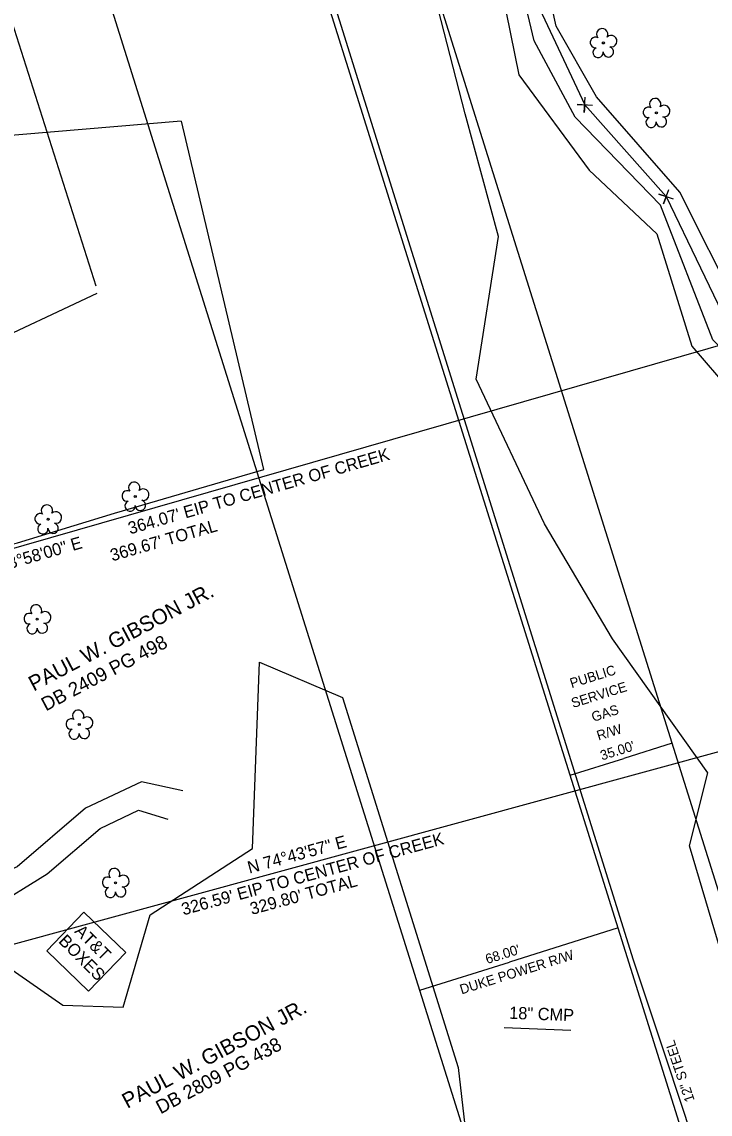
# Model space of a CAD drawing. Extents: x 1380524 to 1382335, y 594765 to 596944.
# Drawn here: x 1381340.7 to 1381565.9, y 595529.8 to 595887.1 of the extents above; entities that cross this region are included whole.
import ezdxf

# ---------------------------------------------------------------- set-up
doc = ezdxf.new("R2010")
doc.units = 0
for name, color, linetype in [('Exist Horizontal Alignment', 7, 'Continuous'), ('Exist Hydro Jurisdictional Stream or Body of Water', 7, 'Continuous'), ('Exist Other Culture Fence Line Text', 7, 'Continuous'), ('Exist Right of Way Line', 7, 'Continuous'), ('Exist Roads EOP', 7, 'Continuous'), ('Exist Structure Major Bridge WW', 7, 'Continuous'), ('Exist Structure Minor Pipes CMP 18 Inch', 7, 'Continuous'), ('Exist Utilities Gas UG Line', 7, 'Continuous'), ('Exist Utilities Gas UG Line SUE', 7, 'Continuous'), ('Exist Utilities Gas UG Line SUE Text', 7, 'Continuous'), ('Exist Utilities Power Tower CELL', 7, 'Continuous'), ('Exist Utilities Power Tower Text', 7, 'Continuous'), ('Prop Approach Slab', 7, 'Continuous'), ('Prop Boundary Easement Permanent Drainage', 7, 'Continuous'), ('Prop Drainage Ditch Base Lines', 7, 'Continuous'), ('Prop Drainage Structure Pipe Elbow CELL', 7, 'Continuous'), ('Prop Drainage Structure Scour Hole CELL', 7, 'Continuous'), ('Prop Earthen Structure Cut Ditch Special Detail Label', 7, 'Continuous'), ('Prop Earthen Structure V Ditch Lateral Detail Label', 7, 'Continuous'), ('Prop Erosion Rip Rap At Embankment Detail CELL', 7, 'Continuous')]:
    doc.layers.add(name, color=color, linetype=linetype)

# ---------------------------------------------------------------- blocks, each defined once
blk = doc.blocks.new('EXIST VEGETATION TREE')
at = {"layer": 'Prop Erosion Rip Rap At Embankment Detail CELL'}
blk.add_line((0, 0), (0, 0), dxfattribs=at)
blk.add_circle((0, 0), 0.00652, dxfattribs=at)
for centre, radius, start, end in [((-0.0077, 0.0575), 0.0371, 330.16508, 219.71335), ((-0.0521, 0.0031), 0.0345, 62.66361, 279.3457), ((0.051, 0.0118), 0.038, 257.1011, 134.19993), ((-0.0341, -0.0624), 0.0338, 111.56708, 6.23104), ((0.0335, -0.058), 0.034, 181.28216, 74.55999)]:
    blk.add_arc(centre, radius, start, end, dxfattribs=at)

msp = doc.modelspace()

# ---------------------------------------------------------------- linework, layer by layer
at = {"layer": 'Exist Horizontal Alignment'}
msp.add_arc((1381427.83, 595653.65), 200, 216.8315, 254.276, dxfattribs=at)
msp.add_arc((1381427.83, 595653.65), 200, 216.8315, 254.276, dxfattribs=at)
msp.add_arc((1381427.83, 595653.65), 200, 216.8315, 254.276, dxfattribs=at)
at = {"layer": 'Exist Hydro Jurisdictional Stream or Body of Water'}
for points in [[(1381577.96, 595605.83), (1381583.71, 595643.65), (1381597.79, 595698.93), (1381598.19, 595737), (1381590.93, 595758.1), (1381566.71, 595783.08), (1381549.63, 595827.2), (1381521.68, 595855.93), (1381508.31, 595880.93), (1381498.43, 595922.32), (1381488.98, 595942.12), (1381494.82, 595973.98), (1381493.85, 596010.61), (1381489.16, 596026.09), (1381477.05, 596042.66), (1381466.32, 596071.54), (1381460.24, 596113.74), (1381470.05, 596141.17)], [(1381591.28, 595608.86), (1381593.5, 595640.64), (1381608.3, 595697.05), (1381607.14, 595736.14), (1381600.89, 595770.21), (1381575.06, 595793.44), (1381555.94, 595831.43), (1381528.67, 595862.58), (1381515.5, 595885.72), (1381506.46, 595926.94), (1381508.98, 595973.98), (1381507.81, 596016.05), (1381489.64, 596056.36), (1381476.02, 596075.92), (1381476.25, 596113.98), (1381483.98, 596135.61)]]:
    msp.add_lwpolyline(points, dxfattribs=at)
at = {"layer": 'Exist Roads EOP'}
for points in [[(1381638.84, 595379.18), (1381451.62, 595975.74)], [(1381605.45, 595368.7), (1381418.22, 595965.25)], [(1381540.57, 595348.34), (1381353.34, 595944.89)]]:
    msp.add_lwpolyline(points, dxfattribs=at)
at = {"layer": 'Exist Structure Major Bridge WW'}
for p, q in [((1381524.86, 595859.94), (1381524.86, 595859.94)), ((1381551.49, 595829.97), (1381551.49, 595829.97))]:
    msp.add_line(p, q, dxfattribs=at)
for points in [[(1381527.36, 595859.79), (1381522.36, 595860.09), (1381524.86, 595859.94), (1381524.71, 595857.44), (1381525.01, 595862.44)], [(1381553.85, 595829.14), (1381549.13, 595830.8), (1381551.49, 595829.97), (1381550.66, 595827.61), (1381552.31, 595832.33)]]:
    msp.add_lwpolyline(points, dxfattribs=at)
at = {"layer": 'Exist Utilities Gas UG Line'}
msp.add_lwpolyline([(1381540.8, 595580.17), (1381404.76, 596015.01)], dxfattribs=at)
at = {"layer": 'Exist Utilities Gas UG Line SUE'}
for p, q in [((1381551.57, 595547.78), (1381540.8, 595580.17)), ((1381564.26, 595509.53), (1381551.57, 595547.78))]:
    msp.add_line(p, q, dxfattribs=at)
at = {"layer": 'Exist Utilities Power Tower CELL'}
for p, q in [((1381553.49, 595651.15), (1381537.66, 595646.18)), ((1381520.09, 595640.67), (1381537.66, 595646.18)), ((1381535.75, 595590.77), (1381500.18, 595579.6)), ((1381470.87, 595570.4), (1381500.18, 595579.6))]:
    msp.add_line(p, q, dxfattribs=at)
at = {"layer": 'Exist Utilities Power Tower Text'}
for p, q in [((1381510.01, 595891.46), (1381524.86, 595859.94)), ((1381524.86, 595859.94), (1381551.49, 595829.97)), ((1381551.49, 595829.97), (1381574.12, 595782.88)), ((1381224.21, 595682.33), (1381574.12, 595782.88)), ((1381276.88, 595568.76), (1381591.94, 595654.76))]:
    msp.add_line(p, q, dxfattribs=at)
at = {"layer": 'Prop Drainage Ditch Base Lines'}
msp.add_lwpolyline([(1381348.83, 595583.31), (1381362.5, 595570.11), (1381374.67, 595582.72), (1381361, 595595.92)], close=True, dxfattribs=at)
at = {"layer": 'Prop Drainage Structure Pipe Elbow CELL'}
for points in [[(1381393.32, 595635.57), (1381379.8, 595638.57), (1381361.52, 595629.98), (1381339.11, 595610.77), (1381323.54, 595604.06), (1381300.42, 595605.15), (1381290.65, 595623.99), (1381271.69, 595614.21), (1381284.47, 595573.49), (1381272.43, 595556.5), (1381266.14, 595553.34)], [(1381285.22, 595530.01), (1381291.89, 595544.25), (1381303.93, 595568.7), (1381309.23, 595589.8), (1381330.17, 595596.89), (1381348.97, 595608.46), (1381366.3, 595623.3), (1381378.81, 595629.23), (1381388.44, 595626.33)]]:
    msp.add_lwpolyline(points, dxfattribs=at)
at = {"layer": 'Prop Drainage Structure Scour Hole CELL'}
msp.add_lwpolyline([(1381498.43, 595558.23), (1381520.27, 595557.36)], dxfattribs=at)
at = {"layer": 'Prop Earthen Structure Cut Ditch Special Detail Label'}
for points in [[(1381632.41, 595523.63), (1381594.41, 595508.73), (1381570.64, 595578.64), (1381559.09, 595617.64), (1381565.11, 595641.47), (1381533.98, 595685.28), (1381511.68, 595722.95), (1381489.27, 595770.29), (1381496.67, 595816.92), (1381485.72, 595857.08), (1381467.95, 595926.31), (1381480.04, 595973.59), (1381453.92, 595980.31), (1381433.25, 596009.07), (1381415.87, 596065.96), (1381400.69, 596114.25), (1381387.34, 596153.1)], [(1381465.14, 596147.24), (1381454.4, 596115.71), (1381460.79, 596073.39), (1381474.76, 596036.69), (1381485.85, 596011.46), (1381489.74, 595978.87), (1381483.02, 595940.04), (1381494.86, 595911.17), (1381503.32, 595869.73), (1381526.27, 595838.58), (1381548.46, 595817.76), (1381559.9, 595781.05), (1381585.35, 595751.36), (1381590.99, 595713.84), (1381582.97, 595667.85), (1381576.78, 595627.99), (1381575.28, 595604.8), (1381583.28, 595579.61), (1381595.01, 595565.4), (1381637.18, 595526.27), (1381634, 595523.66)], [(1381365.22, 595798.28), (1381326.61, 595780.2), (1381306.84, 595815.2), (1381247.89, 595804.83), (1381210.47, 595847.41), (1381176.29, 595840.7), (1381193.99, 595892.72), (1381228.48, 595895.26), (1381260.25, 595890.55), (1381288.84, 595901.2), (1381279.35, 595854.23), (1381302.68, 595848.54), (1381316.62, 595904.23), (1381334.31, 595896.83), (1381364.84, 595800.74)], [(1381311.01, 595552.25), (1381321.59, 595588.1), (1381354.11, 595565.54), (1381373.79, 595564.89), (1381382.69, 595595.08), (1381416.12, 595616.7), (1381418.47, 595677.64), (1381445.54, 595666.13), (1381483.46, 595545.08), (1381491.42, 595475.89), (1381457.51, 595475.03), (1381424.36, 595495.63), (1381355.51, 595508.44), (1381311.33, 595553.4)]]:
    msp.add_lwpolyline(points, dxfattribs=at)
at = {"layer": 'Prop Earthen Structure V Ditch Lateral Detail Label'}
msp.add_lwpolyline([(1381392.81, 595854.66), (1381329.27, 595849.24), (1381290.43, 595845.39), (1381242.5, 595842.5), (1381209.26, 595839.07), (1381178.08, 595837.25), (1381190.93, 595780.69), (1381197.44, 595756.1), (1381206.02, 595718.03), (1381216.97, 595720.51), (1381220.39, 595705.38), (1381228.44, 595683.92), (1381291.34, 595703.48), (1381320.98, 595712.14), (1381339.23, 595716.75), (1381371.02, 595726.37), (1381419.86, 595740.72), (1381392.96, 595854.62)], dxfattribs=at)

# ---------------------------------------------------------------- block references
at = {"layer": 'Prop Erosion Rip Rap At Embankment Detail CELL', "xscale": 50, "yscale": 50}
for p in [(1381530.93, 595880.2), (1381548.27, 595857.33), (1381377.8, 595731.88), (1381349.25, 595724.41), (1381345.73, 595691.75), (1381359.48, 595657.28), (1381371.34, 595605.5)]:
    msp.add_blockref('EXIST VEGETATION TREE', p, dxfattribs=at)

# ---------------------------------------------------------------- texts
at = {"layer": 'Exist Other Culture Fence Line Text'}
for s, rotation, p in [("364.07' EIP TO CENTER OF CREEK", 16.0333, (1381376.09, 595719.46)), ("369.67' TOTAL", 16.0333, (1381370.26, 595710.63)), ('N 73%%D58\'00" E', 16.0333, (1381328.73, 595705.83)), ("326.59' EIP TO CENTER OF CREEK", 15.2676, (1381393.53, 595594.85)), ('N 74%%D43\'57" E', 15.2676, (1381415.13, 595608.5)), ("329.80' TOTAL", 15.2676, (1381415.92, 595594.99))]:
    msp.add_text(s, height=4, rotation=rotation, dxfattribs=at).set_placement(p)
at = {"layer": 'Exist Right of Way Line'}
for rotation, p in [(27.8074, (1381344.55, 595668.04)), (28.1907, (1381375.16, 595531.57))]:
    msp.add_text('PAUL W. GIBSON JR.', height=5, rotation=rotation, dxfattribs=at).set_placement(p)
at = {"layer": 'Exist Structure Minor Pipes CMP 18 Inch'}
for s, rotation, p in [('DB 2409 PG 498', 27.8074, (1381348.54, 595661.56)), ('DB 2809 PG 438', 28.1907, (1381386.06, 595529.76))]:
    msp.add_text(s, height=4.5, rotation=rotation, dxfattribs=at).set_placement(p)
at = {"layer": 'Exist Utilities Gas UG Line SUE Text'}
msp.add_text('12" STEEL', height=3.2, rotation=108.769, dxfattribs=at).set_placement((1381560.85, 595534.44))
at = {"layer": 'Exist Utilities Power Tower CELL'}
for s, p in [('PUBLIC', (1381520.57, 595669.16)), ('SERVICE', (1381521.01, 595662.67)), ('GAS', (1381527.65, 595658.13)), ('R/W', (1381529.35, 595652.03)), ("35.00'", (1381530.5, 595645.53)), ("68.00'", (1381492.94, 595578.93)), ('DUKE POWER R/W', (1381484.56, 595569))]:
    msp.add_text(s, height=3.2, rotation=17.4243, dxfattribs=at).set_placement(p)
at = {"layer": 'Prop Approach Slab'}
for s, p in [('BOXES', (1381352.43, 595586.17)), ('AT&T', (1381357.67, 595589.41))]:
    msp.add_text(s, height=4, rotation=315, dxfattribs=at).set_placement(p)
at = {"layer": 'Prop Boundary Easement Permanent Drainage'}
msp.add_text('18" CMP', height=4, rotation=357.715, dxfattribs=at).set_placement((1381500.06, 595561.06))

doc.saveas('drawing.dxf')
